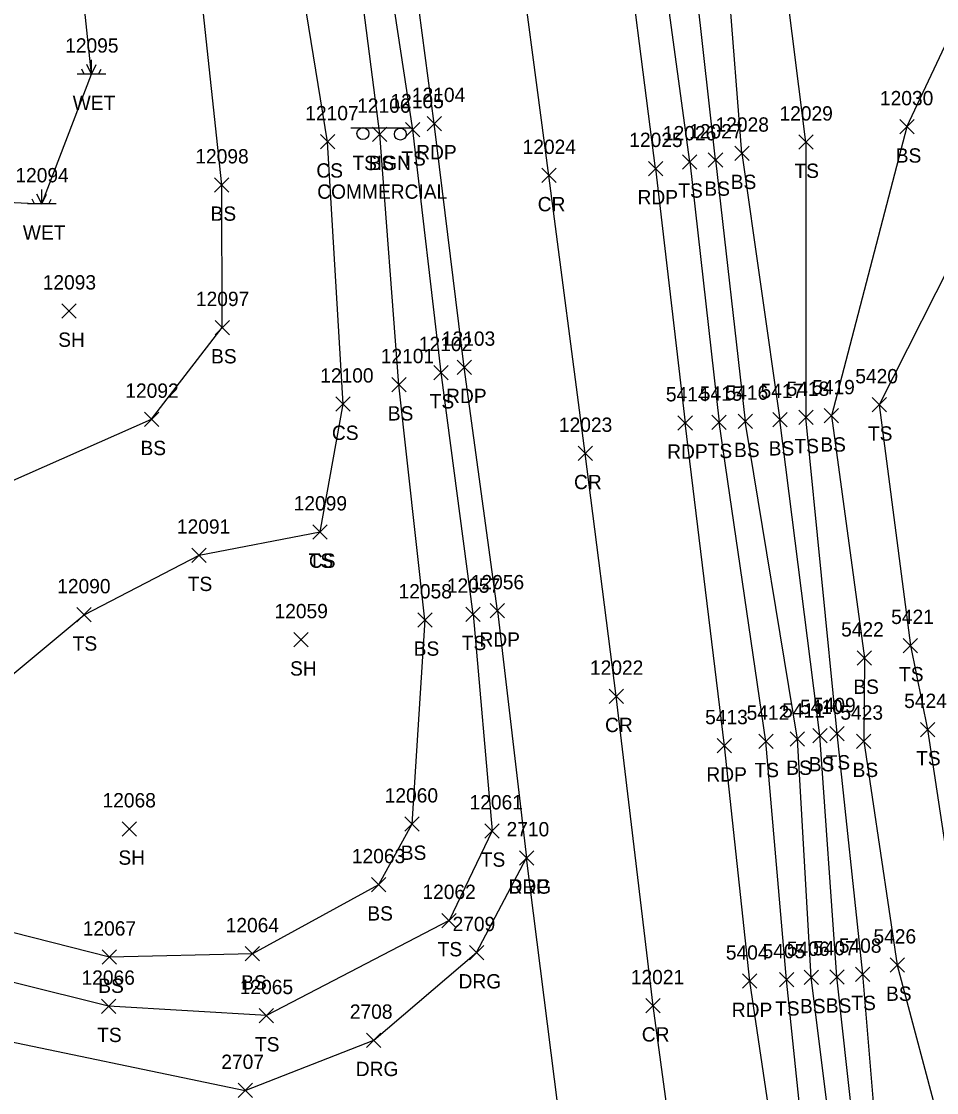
# Model space of a CAD drawing. Extents: x 1439173 to 1457902, y 641926 to 659889.
# Drawn here: x 1447783.4 to 1447910.9, y 649109.6 to 649259.1 of the extents above; entities that cross this region are included whole.
import ezdxf

# ---------------------------------------------------------------- set-up
doc = ezdxf.new("R2010")
doc.units = 0
for name, color, linetype in [('L_A', 7, 'Continuous'), ('L_I', 7, 'Continuous'), ('L_TIC', 7, 'Continuous'), ('LELB', 7, 'Continuous'), ('LWET', 7, 'Continuous'), ('P_A', 7, 'Continuous'), ('P_I', 7, 'Continuous'), ('P_TIC', 7, 'Continuous'), ('PET', 7, 'Continuous'), ('PRC', 7, 'Continuous'), ('R_A', 7, 'Continuous'), ('R_I', 7, 'Continuous'), ('R_TIC', 7, 'Continuous'), ('RDG', 7, 'Continuous'), ('S_A', 7, 'Continuous'), ('S_C', 7, 'Continuous'), ('S_I', 7, 'Continuous'), ('SSGN', 7, 'Continuous')]:
    doc.layers.add(name, color=color, linetype=linetype)

msp = doc.modelspace()

# ---------------------------------------------------------------- linework, layer by layer
at = {"layer": 'L_TIC'}
for points in [[(1447836.91, 649242.97), (1447838.91, 649244.97)], [(1447838.91, 649242.97), (1447836.91, 649244.97)], [(1447905.82, 649243.38), (1447907.82, 649245.38)], [(1447907.82, 649243.38), (1447905.82, 649245.38)], [(1447825.04, 649241.29), (1447827.04, 649243.29)], [(1447827.04, 649241.29), (1447825.04, 649243.29)], [(1447832.33, 649242.34), (1447834.33, 649244.34)], [(1447834.33, 649242.34), (1447832.33, 649244.34)], [(1447891.73, 649241.25), (1447893.73, 649243.25)], [(1447893.73, 649241.25), (1447891.73, 649243.25)], [(1447882.81, 649239.7), (1447884.81, 649241.7)], [(1447884.81, 649239.7), (1447882.81, 649241.7)], [(1447875.53, 649238.49), (1447877.53, 649240.49)], [(1447877.53, 649238.49), (1447875.53, 649240.49)], [(1447879.13, 649238.76), (1447881.13, 649240.76)], [(1447881.13, 649238.76), (1447879.13, 649240.76)], [(1447810.28, 649235.27), (1447812.28, 649237.27)], [(1447812.28, 649235.27), (1447810.28, 649237.27)], [(1447810.28, 649235.27), (1447812.28, 649237.27)], [(1447812.28, 649235.27), (1447810.28, 649237.27)], [(1447789, 649217.68), (1447791, 649219.68)], [(1447791, 649217.68), (1447789, 649219.68)], [(1447810.36, 649215.37), (1447812.36, 649217.37)], [(1447812.36, 649215.37), (1447810.36, 649217.37)], [(1447840.87, 649209.08), (1447842.87, 649211.08)], [(1447842.87, 649209.08), (1447840.87, 649211.08)], [(1447835, 649207.4), (1447837, 649209.4)], [(1447837, 649207.4), (1447835, 649209.4)], [(1447827.21, 649204.69), (1447829.21, 649206.69)], [(1447829.21, 649204.69), (1447827.21, 649206.69)], [(1447901.97, 649204.59), (1447903.97, 649206.59)], [(1447903.97, 649204.59), (1447901.97, 649206.59)], [(1447800.52, 649202.57), (1447802.52, 649204.57)], [(1447802.52, 649202.57), (1447800.52, 649204.57)], [(1447879.62, 649202.16), (1447881.62, 649204.16)], [(1447881.62, 649202.16), (1447879.62, 649204.16)], [(1447883.28, 649202.3), (1447885.28, 649204.3)], [(1447885.28, 649202.3), (1447883.28, 649204.3)], [(1447888.1, 649202.52), (1447890.1, 649204.52)], [(1447890.1, 649202.52), (1447888.1, 649204.52)], [(1447891.74, 649202.84), (1447893.74, 649204.84)], [(1447893.74, 649202.84), (1447891.74, 649204.84)], [(1447895.3, 649203.06), (1447897.3, 649205.06)], [(1447897.3, 649203.06), (1447895.3, 649205.06)], [(1447824, 649186.85), (1447826, 649188.85)], [(1447826, 649186.85), (1447824, 649188.85)], [(1447824, 649186.85), (1447826, 649188.85)], [(1447826, 649186.85), (1447824, 649188.85)], [(1447807.14, 649183.61), (1447809.14, 649185.61)], [(1447809.14, 649183.61), (1447807.14, 649185.61)], [(1447791.1, 649175.29), (1447793.1, 649177.29)], [(1447793.1, 649175.29), (1447791.1, 649177.29)], [(1447845.34, 649175.37), (1447847.34, 649177.37)], [(1447847.34, 649175.37), (1447845.34, 649177.37)], [(1447845.34, 649175.37), (1447847.34, 649177.37)], [(1447847.34, 649175.37), (1447845.34, 649177.37)], [(1447838.61, 649174.58), (1447840.61, 649176.58)], [(1447840.61, 649174.58), (1447838.61, 649176.58)], [(1447838.61, 649174.58), (1447840.61, 649176.58)], [(1447840.61, 649174.58), (1447838.61, 649176.58)], [(1447821.32, 649171.81), (1447823.32, 649173.81)], [(1447823.32, 649171.81), (1447821.32, 649173.81)], [(1447906.31, 649171.01), (1447908.31, 649173.01)], [(1447908.31, 649171.01), (1447906.31, 649173.01)], [(1447899.9, 649169.26), (1447901.9, 649171.26)], [(1447901.9, 649169.26), (1447899.9, 649171.26)], [(1447908.69, 649159.29), (1447910.69, 649161.29)], [(1447910.69, 649159.29), (1447908.69, 649161.29)], [(1447886.16, 649157.64), (1447888.16, 649159.64)], [(1447888.16, 649157.64), (1447886.16, 649159.64)], [(1447890.55, 649157.96), (1447892.55, 649159.96)], [(1447892.55, 649157.96), (1447890.55, 649159.96)], [(1447893.69, 649158.45), (1447895.69, 649160.45)], [(1447895.69, 649158.45), (1447893.69, 649160.45)], [(1447896.07, 649158.71), (1447898.07, 649160.71)], [(1447898.07, 649158.71), (1447896.07, 649160.71)], [(1447899.8, 649157.66), (1447901.8, 649159.66)], [(1447901.8, 649157.66), (1447899.8, 649159.66)], [(1447797.39, 649145.42), (1447799.39, 649147.42)], [(1447799.39, 649145.42), (1447797.39, 649147.42)], [(1447836.81, 649146.1), (1447838.81, 649148.1)], [(1447838.81, 649146.1), (1447836.81, 649148.1)], [(1447847.99, 649145.14), (1447849.99, 649147.14)], [(1447849.99, 649145.14), (1447847.99, 649147.14)], [(1447832.15, 649137.63), (1447834.15, 649139.63)], [(1447834.15, 649137.63), (1447832.15, 649139.63)], [(1447841.98, 649132.64), (1447843.98, 649134.64)], [(1447843.98, 649132.64), (1447841.98, 649134.64)], [(1447794.62, 649127.54), (1447796.62, 649129.54)], [(1447796.62, 649127.54), (1447794.62, 649129.54)], [(1447814.56, 649128), (1447816.56, 649130)], [(1447816.56, 649128), (1447814.56, 649130)], [(1447904.46, 649126.43), (1447906.46, 649128.43)], [(1447906.46, 649126.43), (1447904.46, 649128.43)], [(1447892.47, 649124.7), (1447894.47, 649126.7)], [(1447894.47, 649124.7), (1447892.47, 649126.7)], [(1447896.06, 649124.78), (1447898.06, 649126.78)], [(1447898.06, 649124.78), (1447896.06, 649126.78)], [(1447899.66, 649125.14), (1447901.66, 649127.14)], [(1447901.66, 649125.14), (1447899.66, 649127.14)], [(1447889.03, 649124.37), (1447891.03, 649126.37)], [(1447891.03, 649124.37), (1447889.03, 649126.37)], [(1447794.51, 649120.68), (1447796.51, 649122.68)], [(1447796.51, 649120.68), (1447794.51, 649122.68)], [(1447816.51, 649119.37), (1447818.51, 649121.37)], [(1447818.51, 649119.37), (1447816.51, 649121.37)]]:
    msp.add_lwpolyline(points, dxfattribs=at)
at = {"layer": 'LELB'}
for points in [[(1447846.34, 649176.37), (1447841.87, 649210.08), (1447837.91, 649243.97), (1447832.6, 649279.07), (1447826.01, 649331.58), (1447818.58, 649378.88), (1447810.66, 649418.94), (1447802.04, 649466.23), (1447795.46, 649493.32), (1447784.32, 649538.27), (1447770.47, 649584.57), (1447755.93, 649631.27), (1447739.81, 649673.69), (1447723.82, 649718.23), (1447707.42, 649759.24)], [(1447839.61, 649175.58), (1447836, 649208.4), (1447833.33, 649243.34), (1447828.83, 649278.47), (1447821.05, 649330.93), (1447814.7, 649377.8), (1447805.74, 649417.35), (1447797.64, 649464.98), (1447791.14, 649492.35), (1447780.83, 649537.39), (1447767.13, 649583.58), (1447753.04, 649630.08), (1447736.03, 649672.65), (1447720.84, 649716.55), (1447704.44, 649757.56)], [(1447880.13, 649239.76), (1447875.85, 649278.11), (1447869.91, 649316.47), (1447864.43, 649354.84), (1447857.47, 649403.89), (1447849.64, 649447.67), (1447838.99, 649494.14), (1447825.85, 649553.36), (1447811.08, 649599.11), (1447797.18, 649651.08), (1447779.23, 649693.18), (1447759.75, 649741.89)], [(1447876.53, 649239.49), (1447871.37, 649277.35), (1447866.11, 649316.09), (1447860.32, 649354.49), (1447852.86, 649403.04), (1447844.28, 649446.07), (1447834.7, 649493.13), (1447820.9, 649552.12), (1447807.24, 649597.79), (1447790.92, 649649.39), (1447774.29, 649691.46), (1447755.02, 649740.49)], [(1447883.81, 649240.7), (1447880.79, 649279.34), (1447873.49, 649316.8), (1447868.18, 649355.83), (1447860.86, 649404.8), (1447858.11, 649449.35), (1447845.04, 649496.1), (1447833.8, 649557.16), (1447819.33, 649601.75), (1447806.6, 649653.51)], [(1447892.73, 649242.25), (1447887.93, 649280.36), (1447880.64, 649318.96), (1447878.3, 649357.54), (1447881.11, 649408.37), (1447873.59, 649452.55)], [(1447811.28, 649236.27), (1447807.1, 649275.34), (1447802.06, 649322.6), (1447794.72, 649374.71), (1447783.98, 649413.39)], [(1447825, 649187.85), (1447828.21, 649205.69), (1447826.04, 649242.29), (1447820.46, 649276.62), (1447813.61, 649324.24), (1447804.82, 649376.21), (1447795.7, 649414.81)], [(1447906.82, 649244.38), (1447927.65, 649288.75), (1447928.47, 649335.32)], [(1447922.7, 649244.67), (1447902.97, 649205.59)], [(1447906.82, 649244.38), (1447896.3, 649204.06)], [(1447892.73, 649242.25), (1447892.74, 649203.84)], [(1447883.81, 649240.7), (1447889.1, 649203.52)], [(1447876.53, 649239.49), (1447880.62, 649203.16)], [(1447880.13, 649239.76), (1447884.28, 649203.3)], [(1447839.61, 649175.58), (1447837.81, 649147.1), (1447833.15, 649138.63), (1447815.56, 649129), (1447795.62, 649128.54), (1447771.31, 649134.72), (1447753.09, 649145.83), (1447760.56, 649151.26), (1447773.51, 649167.2), (1447779.27, 649193.76), (1447801.52, 649203.57), (1447811.36, 649216.37), (1447811.28, 649236.27)], [(1447902.97, 649205.59), (1447907.31, 649172.01), (1447909.69, 649160.29), (1447914.36, 649129.28), (1447920.74, 649106.79), (1447931.02, 649086.47)], [(1447898.08, 649050.3), (1447893.41, 649092.69), (1447890.03, 649125.37), (1447887.16, 649158.64), (1447880.62, 649203.16)], [(1447900.31, 649050.61), (1447897.68, 649091.89), (1447893.47, 649125.7), (1447891.55, 649158.96), (1447884.28, 649203.3)], [(1447902.67, 649051.39), (1447900.8, 649091.65), (1447897.06, 649125.78), (1447894.69, 649159.45), (1447889.1, 649203.52)], [(1447909.1, 649052.07), (1447907.78, 649057.72), (1447907.47, 649064.09), (1447906.51, 649067.74), (1447903.62, 649091.01), (1447900.66, 649126.14), (1447897.07, 649159.71), (1447892.74, 649203.84)], [(1447896.3, 649204.06), (1447900.9, 649170.26), (1447900.8, 649158.66), (1447905.46, 649127.43), (1447911.62, 649104.17), (1447931.02, 649086.47)], [(1447846.34, 649176.37), (1447848.99, 649146.14), (1447842.98, 649133.64), (1447817.51, 649120.37), (1447795.51, 649121.68), (1447769.9, 649128.05), (1447753.09, 649145.83), (1447767.92, 649146.78), (1447779.52, 649165.81), (1447792.1, 649176.29), (1447808.14, 649184.61), (1447825, 649187.85)]]:
    msp.add_lwpolyline(points, dxfattribs=at)
at = {"layer": 'LWET'}
for p, q in [((1447793.13, 649251.73), (1447793.13, 649253.73)), ((1447792.13, 649251.73), (1447791.8, 649252.4)), ((1447793.13, 649251.73), (1447792.47, 649253.06)), ((1447793.13, 649251.73), (1447793.8, 649253.06)), ((1447794.13, 649251.73), (1447794.47, 649252.4)), ((1447795.13, 649251.73), (1447791.13, 649251.73)), ((1447786.19, 649233.63), (1447786.19, 649235.63)), ((1447785.19, 649233.63), (1447784.85, 649234.29)), ((1447786.19, 649233.63), (1447785.52, 649234.96)), ((1447786.19, 649233.63), (1447786.85, 649234.96)), ((1447787.19, 649233.63), (1447787.52, 649234.29)), ((1447788.19, 649233.63), (1447784.19, 649233.63))]:
    msp.add_line(p, q, dxfattribs=at)
msp.add_lwpolyline([(1447738.11, 649229.77), (1447758.46, 649234.97), (1447786.19, 649233.63), (1447793.13, 649251.73), (1447790.69, 649275.03), (1447781.7, 649322.13), (1447783.3, 649371.82), (1447773.3, 649412.28), (1447767.38, 649458.17), (1447757.64, 649484.69), (1447747.87, 649528.29), (1447733.18, 649574.64), (1447718.38, 649619.83), (1447701.12, 649663.52), (1447690.28, 649705.63), (1447669.79, 649746.65)], dxfattribs=at)
at = {"layer": 'P_TIC'}
for points in [[(1447839.91, 649243.84), (1447841.91, 649245.84)], [(1447841.91, 649243.84), (1447839.91, 649245.84)], [(1447855.91, 649236.59), (1447857.91, 649238.59)], [(1447857.91, 649236.59), (1447855.91, 649238.59)], [(1447870.78, 649237.56), (1447872.78, 649239.56)], [(1447872.78, 649237.56), (1447870.78, 649239.56)], [(1447844.09, 649209.83), (1447846.09, 649211.83)], [(1447846.09, 649209.83), (1447844.09, 649211.83)], [(1447874.9, 649202.07), (1447876.9, 649204.07)], [(1447876.9, 649202.07), (1447874.9, 649204.07)], [(1447860.97, 649197.82), (1447862.97, 649199.82)], [(1447862.97, 649197.82), (1447860.97, 649199.82)], [(1447848.73, 649175.85), (1447850.73, 649177.85)], [(1447850.73, 649175.85), (1447848.73, 649177.85)], [(1447865.3, 649163.93), (1447867.3, 649165.93)], [(1447867.3, 649163.93), (1447865.3, 649165.93)], [(1447880.37, 649157.03), (1447882.37, 649159.03)], [(1447882.37, 649157.03), (1447880.37, 649159.03)], [(1447852.78, 649141.38), (1447854.78, 649143.38)], [(1447854.78, 649141.38), (1447852.78, 649143.38)], [(1447883.91, 649124.18), (1447885.91, 649126.18)], [(1447885.91, 649124.18), (1447883.91, 649126.18)], [(1447870.42, 649120.75), (1447872.42, 649122.75)], [(1447872.42, 649120.75), (1447870.42, 649122.75)]]:
    msp.add_lwpolyline(points, dxfattribs=at)
at = {"layer": 'PET'}
for points in [[(1447849.73, 649176.85), (1447845.09, 649210.83), (1447840.91, 649244.84), (1447836.3, 649279.67), (1447828.86, 649332.24), (1447821.44, 649379.38), (1447814.07, 649420.15), (1447805.09, 649467.15), (1447798.84, 649494.18), (1447787.3, 649539.51), (1447774.52, 649585.97), (1447758.84, 649632.66), (1447743.77, 649675.2), (1447727.24, 649719.06), (1447711.09, 649760.24)], [(1447871.78, 649238.56), (1447866.81, 649277.49), (1447861.78, 649315.79), (1447855.78, 649353.42), (1447847.68, 649401.96), (1447840.08, 649445.24), (1447830.55, 649491.73), (1447816.67, 649551.63), (1447803.46, 649596.57), (1447786.54, 649647.62), (1447770.26, 649690.21), (1447751.9, 649738.85)], [(1447871.78, 649238.56), (1447875.9, 649203.07)], [(1447894.81, 649050.17), (1447889.75, 649092.62), (1447884.91, 649125.18), (1447881.37, 649158.03), (1447875.9, 649203.07)], [(1447849.73, 649176.85), (1447853.78, 649142.38)]]:
    msp.add_lwpolyline(points, dxfattribs=at)
at = {"layer": 'PRC'}
msp.add_lwpolyline([(1447922.05, 648736.93), (1447916.64, 648778.15), (1447910.27, 648824.18), (1447904.7, 648868.93), (1447898.12, 648915.43), (1447893.31, 648954.8), (1447887.64, 648996.55), (1447880.91, 649046.05), (1447877.83, 649074.56), (1447871.42, 649121.75), (1447866.3, 649164.93), (1447861.97, 649198.82), (1447856.91, 649237.59), (1447851.83, 649275.88), (1447846.3, 649313.42), (1447840.87, 649352.48), (1447833.11, 649400.15), (1447825.79, 649441.89), (1447815.69, 649490.23), (1447802.04, 649547.27), (1447789.05, 649591.57), (1447772.48, 649642.76), (1447756.88, 649685.17), (1447724.87, 649768.37)], dxfattribs=at)
at = {"layer": 'R_TIC'}
for points in [[(1447852.78, 649141.38), (1447854.78, 649143.38)], [(1447854.78, 649141.38), (1447852.78, 649143.38)], [(1447845.82, 649128.16), (1447847.82, 649130.16)], [(1447847.82, 649128.16), (1447845.82, 649130.16)], [(1447831.49, 649115.93), (1447833.49, 649117.93)], [(1447833.49, 649115.93), (1447831.49, 649117.93)], [(1447813.57, 649108.93), (1447815.57, 649110.93)], [(1447815.57, 649108.93), (1447813.57, 649110.93)]]:
    msp.add_lwpolyline(points, dxfattribs=at)
at = {"layer": 'RDG'}
for points in [[(1447712.19, 649289.79), (1447717.6, 649252.13), (1447724.48, 649206.7), (1447729.82, 649176.23), (1447737.91, 649153.41), (1447750.62, 649135.04), (1447776.19, 649117.91), (1447814.57, 649109.93), (1447832.49, 649116.93), (1447846.82, 649129.16), (1447853.78, 649142.38)], [(1447861.1, 649084.28), (1447853.78, 649142.38)]]:
    msp.add_lwpolyline(points, dxfattribs=at)
at = {"layer": 'SSGN'}
for p, q in [((1447829.31, 649244.26), (1447837.91, 649244.26)), ((1447833.33, 649243.36), (1447833.33, 649243.36))]:
    msp.add_line(p, q, dxfattribs=at)
for centre in [(1447830.97, 649243.43), (1447836.19, 649243.36)]:
    msp.add_circle(centre, 0.833, dxfattribs=at)

# ---------------------------------------------------------------- texts
at = {"layer": 'L_A'}
for s, p in [('WET', (1447790.51, 649246.73)), ('BS', (1447831.77, 649238.34)), ('TS', (1447836.32, 649238.97)), ('BS', (1447905.26, 649239.38)), ('CS', (1447824.48, 649237.29)), ('TS', (1447891.14, 649237.25)), ('BS', (1447882.25, 649235.7)), ('TS', (1447874.94, 649234.49)), ('BS', (1447878.58, 649234.76)), ('BS', (1447809.73, 649231.27)), ('BS', (1447809.73, 649231.27)), ('WET', (1447783.56, 649228.63)), ('SH', (1447788.49, 649213.68)), ('BS', (1447809.8, 649211.37)), ('TS', (1447840.28, 649205.08)), ('BS', (1447834.44, 649203.4)), ('CS', (1447826.65, 649200.69)), ('TS', (1447901.38, 649200.59)), ('BS', (1447799.96, 649198.57)), ('TS', (1447879.03, 649198.16)), ('BS', (1447882.72, 649198.3)), ('BS', (1447887.54, 649198.52)), ('TS', (1447891.14, 649198.84)), ('BS', (1447894.74, 649199.06)), ('TS', (1447823.41, 649182.85)), ('CS', (1447823.44, 649182.85)), ('TS', (1447806.55, 649179.61)), ('TS', (1447790.51, 649171.29)), ('TS', (1447844.75, 649171.37)), ('TS', (1447844.75, 649171.37)), ('BS', (1447838.05, 649170.58)), ('BS', (1447838.05, 649170.58)), ('SH', (1447820.81, 649167.81)), ('TS', (1447905.72, 649167.01)), ('BS', (1447899.34, 649165.26)), ('BS', (1447893.13, 649154.45)), ('TS', (1447895.48, 649154.71)), ('TS', (1447908.1, 649155.29)), ('TS', (1447885.57, 649153.64)), ('BS', (1447889.99, 649153.96)), ('BS', (1447899.24, 649153.66)), ('SH', (1447796.88, 649141.42)), ('BS', (1447836.25, 649142.1)), ('TS', (1447847.4, 649141.14)), ('BS', (1447831.59, 649133.63)), ('TS', (1447841.39, 649128.64)), ('BS', (1447794.07, 649123.54)), ('BS', (1447814, 649124)), ('BS', (1447903.9, 649122.43)), ('TS', (1447888.44, 649120.37)), ('BS', (1447891.91, 649120.7)), ('BS', (1447895.5, 649120.78)), ('TS', (1447899.07, 649121.14)), ('TS', (1447793.92, 649116.68)), ('TS', (1447815.92, 649115.37))]:
    msp.add_text(s, height=2, dxfattribs=at).set_placement(p)
at = {"layer": 'L_I'}
for s, p in [('12095', (1447789.46, 649254.73)), ('12105', (1447834.81, 649246.97)), ('12030', (1447903.06, 649247.38)), ('12106', (1447830.17, 649246.34)), ('12107', (1447822.94, 649245.29)), ('12029', (1447889.05, 649245.25)), ('12026', (1447872.8, 649242.49)), ('12027', (1447876.46, 649242.76)), ('12028', (1447880.14, 649243.7)), ('12098', (1447807.61, 649239.27)), ('12098', (1447807.61, 649239.27)), ('12094', (1447782.52, 649236.63)), ('12093', (1447786.33, 649221.68)), ('12097', (1447807.69, 649219.37)), ('12102', (1447838.77, 649213.08)), ('12101', (1447833.46, 649211.4)), ('12100', (1447825.02, 649208.69)), ('5420', (1447899.62, 649208.59)), ('12092', (1447797.85, 649206.57)), ('5418', (1447890.04, 649206.84)), ('5419', (1447893.6, 649207.06)), ('5415', (1447877.93, 649206.16)), ('5416', (1447881.53, 649206.3)), ('5417', (1447886.41, 649206.52)), ('12099', (1447821.32, 649190.85)), ('12099', (1447821.32, 649190.85)), ('12091', (1447805.04, 649187.61)), ('12090', (1447788.35, 649179.29)), ('12058', (1447835.94, 649178.58)), ('12058', (1447835.94, 649178.58)), ('12057', (1447842.67, 649179.37)), ('12057', (1447842.67, 649179.37)), ('12059', (1447818.65, 649175.81)), ('5421', (1447904.62, 649175.01)), ('5422', (1447897.64, 649173.26)), ('5424', (1447906.43, 649163.29)), ('5411', (1447889.42, 649161.96)), ('5410', (1447891.91, 649162.45)), ('5409', (1447893.72, 649162.71)), ('5412', (1447884.47, 649161.64)), ('5423', (1447897.54, 649161.66)), ('12060', (1447834.01, 649150.1)), ('12068', (1447794.67, 649149.42)), ('12061', (1447845.84, 649149.14)), ('12063', (1447829.43, 649141.63)), ('12062', (1447839.27, 649136.64)), ('12064', (1447811.84, 649132)), ('12067', (1447791.91, 649131.54)), ('5426', (1447902.15, 649130.43)), ('5408', (1447897.32, 649129.14)), ('5405', (1447886.69, 649128.37)), ('5406', (1447890.08, 649128.7)), ('5407', (1447893.72, 649128.78)), ('12066', (1447791.74, 649124.68)), ('12065', (1447813.8, 649123.37))]:
    msp.add_text(s, height=2, dxfattribs=at).set_placement(p)
at = {"layer": 'P_A'}
for s, p in [('RDP', (1447838.4, 649239.84)), ('RDP', (1447869.26, 649233.56)), ('CR', (1447855.34, 649232.59)), ('RDP', (1447842.57, 649205.83)), ('RDP', (1447873.39, 649198.07)), ('CR', (1447860.4, 649193.82)), ('RDP', (1447847.22, 649171.85)), ('CR', (1447864.73, 649159.93)), ('RDP', (1447878.86, 649153.03)), ('RDP', (1447851.27, 649137.38)), ('RDP', (1447882.4, 649120.18)), ('CR', (1447869.85, 649116.75))]:
    msp.add_text(s, height=2, dxfattribs=at).set_placement(p)
at = {"layer": 'P_I'}
for s, p in [('12104', (1447837.81, 649247.84)), ('12025', (1447868.11, 649241.56)), ('12024', (1447853.24, 649240.59)), ('12103', (1447841.98, 649213.83)), ('5414', (1447873.21, 649206.07)), ('12023', (1447858.3, 649201.82)), ('12056', (1447846.01, 649179.85)), ('12022', (1447862.63, 649167.93)), ('5413', (1447878.68, 649161.03)), ('2710', (1447851, 649145.38)), ('5404', (1447881.57, 649128.18)), ('12021', (1447868.32, 649124.75))]:
    msp.add_text(s, height=2, dxfattribs=at).set_placement(p)
at = {"layer": 'R_A'}
for p in [(1447851.27, 649137.38), (1447844.31, 649124.16), (1447829.98, 649111.93)]:
    msp.add_text('DRG', height=2, dxfattribs=at).set_placement(p)
at = {"layer": 'R_I'}
for s, p in [('2710', (1447851, 649145.38)), ('2709', (1447843.47, 649132.16)), ('2708', (1447829.15, 649119.93)), ('2707', (1447811.23, 649112.93))]:
    msp.add_text(s, height=2, dxfattribs=at).set_placement(p)
at = {"layer": 'S_A'}
msp.add_text('TSIGN', height=2, dxfattribs=at).set_placement((1447829.51, 649238.34))
at = {"layer": 'S_C'}
msp.add_text('COMMERCIAL', height=2, dxfattribs=at).set_placement((1447824.6, 649234.34))
at = {"layer": 'S_I'}
msp.add_text('12106', height=2, dxfattribs=at).set_placement((1447830.17, 649246.34))

doc.saveas('drawing.dxf')
